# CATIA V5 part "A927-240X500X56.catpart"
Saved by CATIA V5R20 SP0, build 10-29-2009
Part number: A927-240X500X56
Source: Unknown
Property "A": "160.000"
Property "ARTICLENO": "A927-240X500X56"
Property "BOMINFO": "A927-240X500X56"
Property "CODE": "A927-240X500X56"
Property "CREATOR": "CADENAS GmbH"
Property "D": "26.000"
Property "D1": "40.000"
Property "F": "36.000"
Property "FORM": "B"
Property "L": "500.000"
Property "L1": "250.000"
Property "L2": "40.000"
Property "L3": "160.000"
Property "LINA": "A927-240X500X56"
Property "NB": "A927-240X500X56"
Property "NBSYN": "$CODE."
Property "NN": "A927"
Property "NT": "VDI 3387 Removable Die Heels, steel and self-lubricating"
Property "R": "31.500"
Property "S": "56.000"
Property "SUPPLIER": "CF"
Property "T": "30.500"
Property "W": "240.000"
Bounding box of the stored display mesh (mm): x -120 to 120, y 0 to 500, z -56 to 0
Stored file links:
  C:\Users\borellobunino\Desktop\3D X SITO CF\A927\GSB_OILLESS_G2290524050056\CATIAV5\A927-240X500X56.catpart
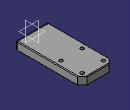
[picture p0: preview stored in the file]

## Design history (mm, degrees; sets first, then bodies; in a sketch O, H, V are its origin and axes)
Body1 "Geometry.1" (main body)
  Solid1 "A927-240X500X56.catpart": solid without history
